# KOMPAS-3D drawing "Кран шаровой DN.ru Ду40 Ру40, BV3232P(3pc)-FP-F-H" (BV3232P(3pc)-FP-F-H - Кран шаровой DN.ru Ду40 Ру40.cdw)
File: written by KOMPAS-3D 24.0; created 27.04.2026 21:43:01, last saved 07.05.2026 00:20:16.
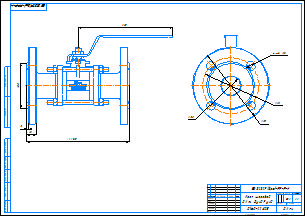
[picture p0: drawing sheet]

Document properties: Автор: Максим; Форматы листов документа: A2; Полное имя файла: BVxxP(3pc)-FP-F-H - Кран шаровой DN.ru Ду40 Ру40.cdw; Масса: 6.105; Наименование: Кран шаровой DN.ru Ду40 Ру40; Количество листов документа: 1; Примечание: D160-22805

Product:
- Body: Тело 1  | qty 1
    Масса: 6.973798
- Part/product: Кран шаровой DN.ru Ду40 Ру40  | designation BV3232P(3pc)-FP-F-H
    Масса: 6.105
    Раздел спецификации: Прочие изделия
    Форматы листов документа: A2
    Примечание: D160-22805

Views: Вид 1, Вид:1, Проекционный вид 2
Referenced files in D:\Rabota ebanaya\Апрель\BVxxP(3pc)-FP-F-H Кран шаровой Ду15-100\Типоразмеры\DN40\: BVxxP(3pc)-FP-F-H - Кран шаровой DN.ru Ду40 Ру40.m3d
Referenced files in D:\Rabota ebanaya\Апрель\BV3232P(3pc)-FP-F-H Кран шаровой Ду15-100\Исходники\DN40\: BV3232P(3pc)-FP-F-H - Кран шаровой DN.ru Ду40 Ру40.m3d
Referenced files in D:\Rabota ebanaya\Апрель\BVxxP(3pc)-FP-F-H Кран шаровой Ду15-100\Исходники\DN40\: BVxxP(3pc)-FP-F-H - Кран шаровой DN.ru Ду40 Ру40.cdw
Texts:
  Линейный размер
  BV3232P(3pc)-FP-F-H
  Диаметральный размер
  Кран шаровой
  DN.ru Ду40 Ру40
  Кран шаровой DN.ru Ду40 Ру40
  BV3232P(3pc)-FP-F-H Кран шаровой DN.ru Ду40 Ру40
Dimensions and other numbers on the sheet: 0; 3; 2; 4; 200±1,5; 88; 185; 18; 150; 38; 110; 4 отв.; 1:1; 1; 6,11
